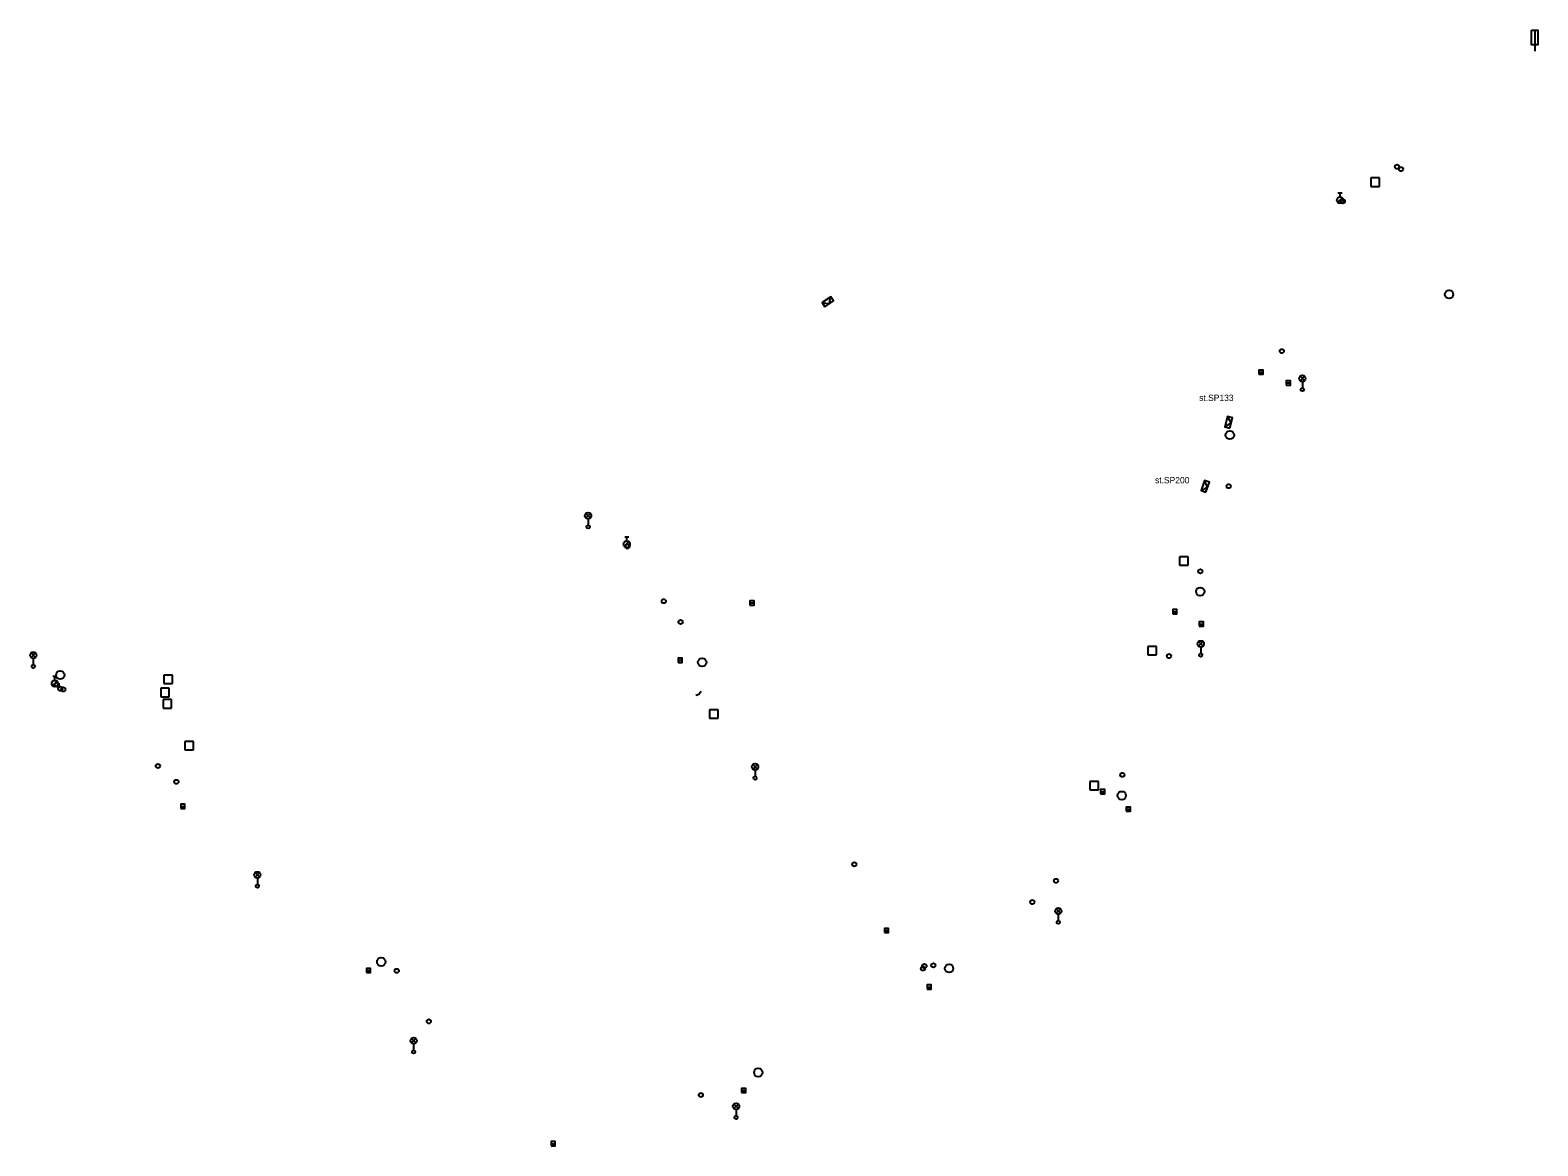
# Model space of a CAD drawing. Extents: x -762383 to -761269, y -1154974 to -1154183.
# Drawn here: x -761755.7 to -761577.1, y -1154637.9 to -1154505.7 of the extents above; entities that cross this region are included whole.
import ezdxf

# ---------------------------------------------------------------- set-up
doc = ezdxf.new("R2010")
doc.units = 0
for name, color, linetype in [('Vrstva 1', 7, 'Continuous'), ('Vrstva 11', 7, 'Continuous'), ('Vrstva 2', 7, 'Continuous'), ('Vrstva 5', 7, 'Continuous'), ('Vrstva 9', 7, 'Continuous')]:
    doc.layers.add(name, color=color, linetype=linetype)

msp = doc.modelspace()

# ---------------------------------------------------------------- linework, layer by layer
at = {"layer": 'Vrstva 1'}
for points in [[(-761661.526, -1154538.502), (-761660.494, -1154537.798), (-761660.832, -1154537.302), (-761661.864, -1154538.007)], [(-761613.559, -1154552.854), (-761613.241, -1154551.646), (-761613.821, -1154551.493), (-761614.139, -1154552.702)], [(-761616.402, -1154560.448), (-761615.978, -1154559.272), (-761616.543, -1154559.069), (-761616.966, -1154560.245)]]:
    msp.add_lwpolyline(points, close=True, dxfattribs=at)
for points in [[(-761661.864, -1154538.007), (-761661.01, -1154538.15), (-761660.832, -1154537.302)], [(-761614.139, -1154552.702), (-761613.4, -1154552.25), (-761613.821, -1154551.493)], [(-761616.966, -1154560.245), (-761616.19, -1154559.86), (-761616.543, -1154559.069)]]:
    msp.add_lwpolyline(points, dxfattribs=at)
at = {"layer": 'Vrstva 11'}
msp.add_lwpolyline([(-761676.8, -1154584.51), (-761676.45, -1154584.37), (-761676.18, -1154584.04)], dxfattribs=at)
at = {"layer": 'Vrstva 5'}
for points in [[(-761577.825, -1154505.73), (-761577.075, -1154505.73), (-761577.075, -1154507.48), (-761577.825, -1154507.48), (-761577.825, -1154505.73)], [(-761577.45, -1154505.73), (-761577.45, -1154508.23)]]:
    msp.add_lwpolyline(points, dxfattribs=at)
at = {"layer": 'Vrstva 9'}
for p, q in [((-761595.85, -1154523.23), (-761596.85, -1154523.23)), ((-761596.85, -1154523.23), (-761596.85, -1154524.23)), ((-761595.85, -1154524.23), (-761595.85, -1154523.23)), ((-761600.75, -1154524.985), (-761600.25, -1154524.985)), ((-761600.5, -1154525.485), (-761600.5, -1154524.985)), ((-761596.85, -1154524.23), (-761595.85, -1154524.23)), ((-761600.794, -1154526.091), (-761600.204, -1154525.628)), ((-761610.12, -1154546.24), (-761609.62, -1154546.24)), ((-761605.234, -1154547.248), (-761604.706, -1154546.72)), ((-761604.698, -1154547.245), (-761605.226, -1154546.716)), ((-761606.87, -1154547.51), (-761606.37, -1154547.51)), ((-761604.97, -1154547.36), (-761604.97, -1154548.11)), ((-761689.834, -1154563.508), (-761689.306, -1154562.98)), ((-761689.298, -1154563.505), (-761689.826, -1154562.976)), ((-761689.57, -1154563.62), (-761689.57, -1154564.37)), ((-761685.284, -1154566.851), (-761684.694, -1154566.388)), ((-761685.24, -1154565.745), (-761684.74, -1154565.745)), ((-761684.99, -1154566.245), (-761684.99, -1154565.745)), ((-761618.51, -1154568.12), (-761619.51, -1154568.12)), ((-761619.51, -1154568.12), (-761619.51, -1154569.12)), ((-761618.51, -1154569.12), (-761618.51, -1154568.12)), ((-761619.51, -1154569.12), (-761618.51, -1154569.12)), ((-761670.41, -1154573.58), (-761669.91, -1154573.58)), ((-761620.33, -1154574.62), (-761619.83, -1154574.62)), ((-761617.18, -1154576.08), (-761616.68, -1154576.08)), ((-761622.26, -1154578.72), (-761623.26, -1154578.72)), ((-761623.26, -1154578.72), (-761623.26, -1154579.72)), ((-761622.26, -1154579.72), (-761622.26, -1154578.72)), ((-761617.264, -1154578.688), (-761616.736, -1154578.16)), ((-761616.728, -1154578.685), (-761617.256, -1154578.156)), ((-761617, -1154578.8), (-761617, -1154579.55)), ((-761755.554, -1154580.028), (-761755.026, -1154579.5)), ((-761755.018, -1154580.025), (-761755.546, -1154579.496)), ((-761755.29, -1154580.14), (-761755.29, -1154580.89)), ((-761678.92, -1154580.36), (-761678.42, -1154580.36)), ((-761623.26, -1154579.72), (-761622.26, -1154579.72)), ((-761752.99, -1154582.245), (-761752.49, -1154582.245)), ((-761752.74, -1154582.745), (-761752.74, -1154582.245)), ((-761738.82, -1154582.12), (-761739.82, -1154582.12)), ((-761739.82, -1154582.12), (-761739.82, -1154583.12)), ((-761738.82, -1154583.12), (-761738.82, -1154582.12)), ((-761753.034, -1154583.351), (-761752.444, -1154582.888)), ((-761739.18, -1154583.68), (-761740.18, -1154583.68)), ((-761740.18, -1154583.68), (-761740.18, -1154584.68)), ((-761739.82, -1154583.12), (-761738.82, -1154583.12)), ((-761739.18, -1154584.68), (-761739.18, -1154583.68)), ((-761740.18, -1154584.68), (-761739.18, -1154584.68)), ((-761738.92, -1154585.02), (-761739.92, -1154585.02)), ((-761739.92, -1154585.02), (-761739.92, -1154586.02)), ((-761739.92, -1154586.02), (-761738.92, -1154586.02)), ((-761738.92, -1154586.02), (-761738.92, -1154585.02)), ((-761674.18, -1154586.22), (-761675.18, -1154586.22)), ((-761675.18, -1154586.22), (-761675.18, -1154587.22)), ((-761675.18, -1154587.22), (-761674.18, -1154587.22)), ((-761674.18, -1154587.22), (-761674.18, -1154586.22)), ((-761736.33, -1154589.98), (-761737.33, -1154589.98)), ((-761737.33, -1154589.98), (-761737.33, -1154590.98)), ((-761737.33, -1154590.98), (-761736.33, -1154590.98)), ((-761736.33, -1154590.98), (-761736.33, -1154589.98)), ((-761670.054, -1154593.248), (-761669.526, -1154592.72)), ((-761669.518, -1154593.245), (-761670.046, -1154592.716)), ((-761669.79, -1154593.36), (-761669.79, -1154594.11)), ((-761629.13, -1154594.72), (-761630.13, -1154594.72)), ((-761630.13, -1154594.72), (-761630.13, -1154595.72)), ((-761629.13, -1154595.72), (-761629.13, -1154594.72)), ((-761630.13, -1154595.72), (-761629.13, -1154595.72)), ((-761628.88, -1154595.94), (-761628.38, -1154595.94)), ((-761737.83, -1154597.67), (-761737.33, -1154597.67)), ((-761625.82, -1154598), (-761625.32, -1154598)), ((-761729.014, -1154606.048), (-761728.486, -1154605.52)), ((-761728.478, -1154606.045), (-761729.006, -1154605.516)), ((-761728.75, -1154606.16), (-761728.75, -1154606.91)), ((-761634.144, -1154610.338), (-761633.616, -1154609.81)), ((-761633.608, -1154610.335), (-761634.136, -1154609.806)), ((-761633.88, -1154610.45), (-761633.88, -1154611.2)), ((-761654.48, -1154612.37), (-761653.98, -1154612.37)), ((-761715.84, -1154617.11), (-761715.34, -1154617.11)), ((-761649.42, -1154619.07), (-761648.92, -1154619.07)), ((-761710.504, -1154625.688), (-761709.976, -1154625.16)), ((-761709.968, -1154625.685), (-761710.496, -1154625.156)), ((-761710.24, -1154625.8), (-761710.24, -1154626.55)), ((-761671.41, -1154631.32), (-761670.91, -1154631.32)), ((-761672.304, -1154633.458), (-761671.776, -1154632.93)), ((-761671.768, -1154633.455), (-761672.296, -1154632.926)), ((-761672.04, -1154633.57), (-761672.04, -1154634.32)), ((-761693.96, -1154637.63), (-761693.46, -1154637.63))]:
    msp.add_line(p, q, dxfattribs=at)
for points in [[(-761610.12, -1154546.491), (-761609.62, -1154546.491), (-761609.62, -1154545.99), (-761610.12, -1154545.99)], [(-761606.87, -1154547.761), (-761606.37, -1154547.761), (-761606.37, -1154547.26), (-761606.87, -1154547.26)], [(-761670.41, -1154573.831), (-761669.91, -1154573.831), (-761669.91, -1154573.33), (-761670.41, -1154573.33)], [(-761620.33, -1154574.871), (-761619.83, -1154574.871), (-761619.83, -1154574.37), (-761620.33, -1154574.37)], [(-761617.18, -1154576.331), (-761616.68, -1154576.331), (-761616.68, -1154575.83), (-761617.18, -1154575.83)], [(-761678.92, -1154580.611), (-761678.42, -1154580.611), (-761678.42, -1154580.11), (-761678.92, -1154580.11)], [(-761628.88, -1154596.191), (-761628.38, -1154596.191), (-761628.38, -1154595.69), (-761628.88, -1154595.69)], [(-761737.83, -1154597.921), (-761737.33, -1154597.921), (-761737.33, -1154597.42), (-761737.83, -1154597.42)], [(-761625.82, -1154598.251), (-761625.32, -1154598.251), (-761625.32, -1154597.75), (-761625.82, -1154597.75)], [(-761654.48, -1154612.621), (-761653.98, -1154612.621), (-761653.98, -1154612.12), (-761654.48, -1154612.12)], [(-761715.84, -1154617.361), (-761715.34, -1154617.361), (-761715.34, -1154616.86), (-761715.84, -1154616.86)], [(-761649.42, -1154619.321), (-761648.92, -1154619.321), (-761648.92, -1154618.82), (-761649.42, -1154618.82)], [(-761671.41, -1154631.571), (-761670.91, -1154631.571), (-761670.91, -1154631.07), (-761671.41, -1154631.07)], [(-761693.96, -1154637.881), (-761693.46, -1154637.881), (-761693.46, -1154637.38), (-761693.96, -1154637.38)]]:
    msp.add_lwpolyline(points, close=True, dxfattribs=at)
for centre, radius in [((-761593.76, -1154521.91), 0.25), ((-761593.29, -1154522.19), 0.25), ((-761600.5, -1154525.86), 0.375), ((-761600.17, -1154526), 0.25), ((-761587.59, -1154537.03), 0.5), ((-761607.4, -1154543.75), 0.25), ((-761604.97, -1154546.985), 0.375), ((-761604.97, -1154548.31), 0.2), ((-761613.56, -1154553.69), 0.5), ((-761613.7, -1154559.75), 0.25), ((-761689.57, -1154563.245), 0.375), ((-761689.57, -1154564.57), 0.2), ((-761684.99, -1154566.62), 0.375), ((-761684.92, -1154566.88), 0.25), ((-761617.05, -1154569.83), 0.25), ((-761617.06, -1154572.23), 0.5), ((-761680.61, -1154573.37), 0.25), ((-761678.62, -1154575.83), 0.25), ((-761617, -1154578.425), 0.375), ((-761755.29, -1154579.765), 0.375), ((-761676.06, -1154580.61), 0.5), ((-761620.76, -1154579.87), 0.25), ((-761617, -1154579.75), 0.2), ((-761755.29, -1154581.09), 0.2), ((-761752.1, -1154582.12), 0.5), ((-761752.74, -1154583.12), 0.375), ((-761752.5, -1154583.26), 0.25), ((-761752.09, -1154583.74), 0.25), ((-761751.74, -1154583.82), 0.25), ((-761740.53, -1154592.89), 0.25), ((-761669.79, -1154592.985), 0.375), ((-761738.34, -1154594.76), 0.25), ((-761669.79, -1154594.31), 0.2), ((-761626.3, -1154593.94), 0.25), ((-761626.36, -1154596.39), 0.5), ((-761728.75, -1154605.785), 0.375), ((-761658.04, -1154604.54), 0.25), ((-761728.75, -1154607.11), 0.2), ((-761634.15, -1154606.49), 0.25), ((-761636.96, -1154609.01), 0.25), ((-761633.88, -1154610.075), 0.375), ((-761633.88, -1154611.4), 0.2), ((-761714.08, -1154616.08), 0.5), ((-761649.74, -1154616.59), 0.25), ((-761648.68, -1154616.5), 0.25), ((-761646.82, -1154616.86), 0.5), ((-761712.24, -1154617.15), 0.25), ((-761649.91, -1154616.88), 0.25), ((-761708.44, -1154623.14), 0.25), ((-761710.24, -1154625.425), 0.375), ((-761710.24, -1154626.75), 0.2), ((-761669.42, -1154629.19), 0.5), ((-761676.22, -1154631.86), 0.25), ((-761672.04, -1154633.195), 0.375), ((-761672.04, -1154634.52), 0.2)]:
    msp.add_circle(centre, radius, dxfattribs=at)

# ---------------------------------------------------------------- texts
at = {"layer": 'Vrstva 2'}
for s, p in [('st.SP133', (-761617.19, -1154549.65)), ('st.SP200', (-761622.42, -1154559.41))]:
    msp.add_text(s, height=0.75, dxfattribs=at).set_placement(p)

doc.saveas('drawing.dxf')
